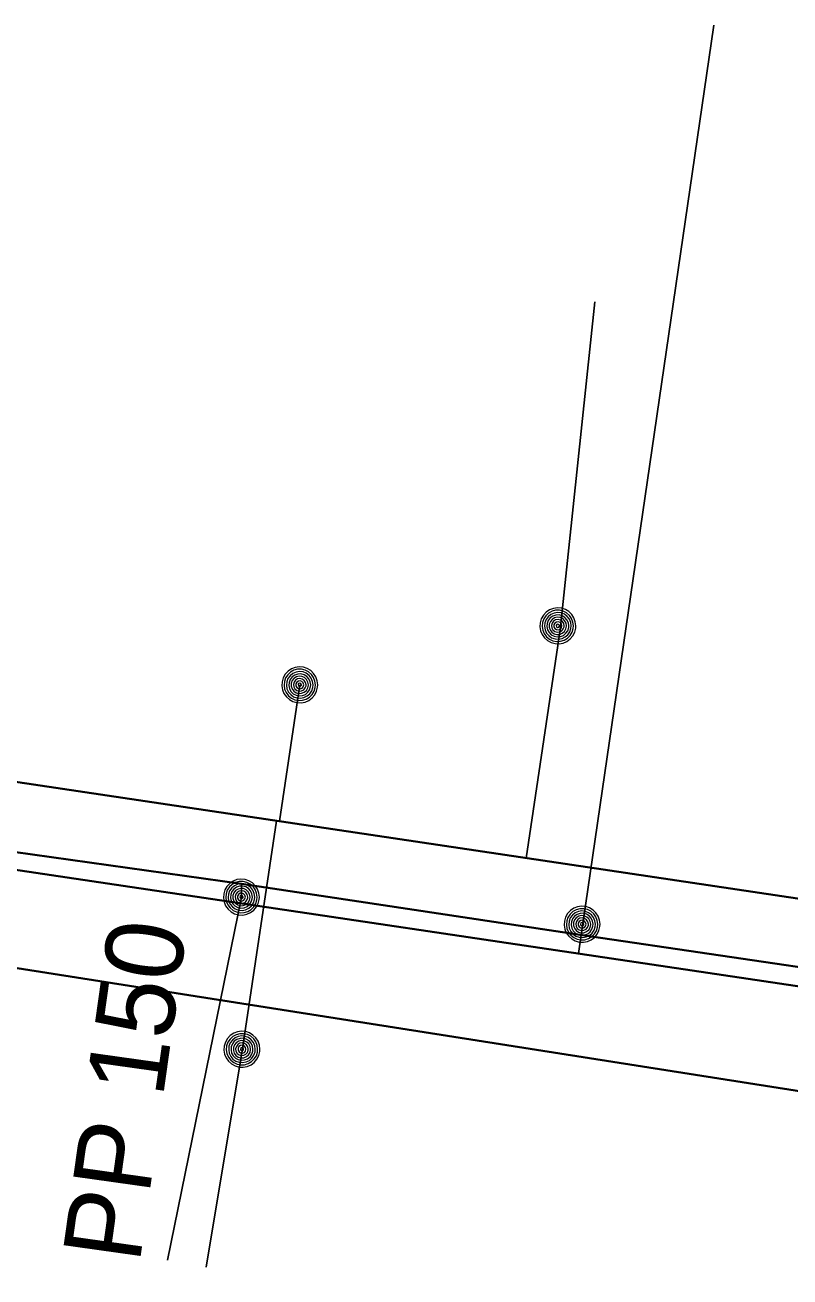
# Model space of a CAD drawing. Extents: x -866761 to -866592, y -1013996 to -1013877.
# Drawn here: x -866692.58 to -866682.75, y -1013971.12 to -1013955.01 of the extents above; entities that cross this region are included whole.
import ezdxf

# ---------------------------------------------------------------- set-up
doc = ezdxf.new("R2010")
doc.units = 0
doc.header["$LTSCALE"] = 0.44
for name, color, linetype, lineweight in [('1', 7, 'Continuous', 35), ('12', 7, 'Continuous', 13), ('21', 7, 'Continuous', 35), ('23', 7, 'Continuous', 25), ('25', 7, 'Continuous', 13), ('3', 7, 'Continuous', 25), ('32', 7, 'Continuous', 13)]:
    doc.layers.add(name, color=color, linetype=linetype, lineweight=lineweight)

msp = doc.modelspace()

# ---------------------------------------------------------------- linework, layer by layer
at = {"layer": '1'}
msp.add_line((-866612.967, -1013977.763), (-866734.931, -1013959.586), dxfattribs=at)
for points in [[(-866612.815, -1013977.108), (-866621.035, -1013976.325), (-866621.378, -1013976.297), (-866626.243, -1013975.519), (-866632.94, -1013974.51), (-866645.03, -1013972.86), (-866647.305, -1013972.501), (-866654.48, -1013971.31), (-866668.882, -1013969.171), (-866678.229, -1013967.78), (-866685.446, -1013966.718), (-866689.8, -1013966.06), (-866697.865, -1013964.927), (-866723.097, -1013961.352), (-866726.923, -1013960.77), (-866727.214, -1013960.734), (-866737.38, -1013959.64), (-866746.09, -1013958.48), (-866747.84, -1013958.25), (-866748.13, -1013958.99), (-866750.15, -1013958.69)], [(-866613.338, -1013979.363), (-866624.951, -1013977.802), (-866715.256, -1013963.593), (-866735.102, -1013960.577)]]:
    msp.add_lwpolyline(points, dxfattribs=at)
at = {"layer": '12'}
for points in [[(-866689.569, -1013966.23), (-866689.575, -1013966.178), (-866689.592, -1013966.128), (-866689.621, -1013966.084), (-866689.658, -1013966.047), (-866689.703, -1013966.02), (-866689.753, -1013966.003), (-866689.806, -1013965.999), (-866689.858, -1013966.006), (-866689.907, -1013966.025), (-866689.95, -1013966.054), (-866689.986, -1013966.093), (-866690.012, -1013966.138), (-866690.028, -1013966.189), (-866690.031, -1013966.241), (-866690.023, -1013966.293), (-866690.003, -1013966.342), (-866689.972, -1013966.385), (-866689.933, -1013966.419), (-866689.887, -1013966.445), (-866689.836, -1013966.459), (-866689.783, -1013966.461), (-866689.732, -1013966.451), (-866689.684, -1013966.43), (-866689.641, -1013966.399), (-866689.607, -1013966.358), (-866689.583, -1013966.312), (-866689.571, -1013966.261)], [(-866689.599, -1013966.23), (-866689.605, -1013966.181), (-866689.622, -1013966.135), (-866689.65, -1013966.095), (-866689.687, -1013966.063), (-866689.731, -1013966.041), (-866689.779, -1013966.03), (-866689.828, -1013966.03), (-866689.875, -1013966.043), (-866689.918, -1013966.067), (-866689.954, -1013966.1), (-866689.981, -1013966.141), (-866689.997, -1013966.188), (-866690.001, -1013966.237), (-866689.994, -1013966.285), (-866689.975, -1013966.33), (-866689.945, -1013966.37), (-866689.907, -1013966.401), (-866689.863, -1013966.421), (-866689.815, -1013966.431), (-866689.766, -1013966.429), (-866689.719, -1013966.414), (-866689.676, -1013966.389), (-866689.642, -1013966.355), (-866689.616, -1013966.313), (-866689.602, -1013966.266)], [(-866689.629, -1013966.23), (-866689.635, -1013966.185), (-866689.652, -1013966.143), (-866689.68, -1013966.108), (-866689.716, -1013966.081), (-866689.758, -1013966.064), (-866689.803, -1013966.059), (-866689.848, -1013966.065), (-866689.889, -1013966.084), (-866689.924, -1013966.112), (-866689.951, -1013966.149), (-866689.967, -1013966.191), (-866689.971, -1013966.236), (-866689.964, -1013966.281), (-866689.945, -1013966.322), (-866689.916, -1013966.356), (-866689.879, -1013966.382), (-866689.836, -1013966.398), (-866689.791, -1013966.401), (-866689.746, -1013966.393), (-866689.706, -1013966.373), (-866689.672, -1013966.344), (-866689.646, -1013966.306), (-866689.632, -1013966.263)], [(-866689.659, -1013966.23), (-866689.664, -1013966.189), (-866689.682, -1013966.152), (-866689.709, -1013966.121), (-866689.744, -1013966.1), (-866689.784, -1013966.089), (-866689.825, -1013966.091), (-866689.864, -1013966.104), (-866689.898, -1013966.128), (-866689.923, -1013966.16), (-866689.938, -1013966.198), (-866689.941, -1013966.239), (-866689.933, -1013966.279), (-866689.913, -1013966.315), (-866689.884, -1013966.344), (-866689.847, -1013966.363), (-866689.807, -1013966.371), (-866689.766, -1013966.367), (-866689.728, -1013966.352), (-866689.696, -1013966.326), (-866689.673, -1013966.292), (-866689.66, -1013966.253)], [(-866689.689, -1013966.23), (-866689.694, -1013966.194), (-866689.712, -1013966.162), (-866689.738, -1013966.137), (-866689.772, -1013966.122), (-866689.808, -1013966.119), (-866689.843, -1013966.127), (-866689.874, -1013966.147), (-866689.897, -1013966.175), (-866689.91, -1013966.209), (-866689.91, -1013966.246), (-866689.899, -1013966.281), (-866689.878, -1013966.31), (-866689.848, -1013966.331), (-866689.813, -1013966.341), (-866689.776, -1013966.339), (-866689.742, -1013966.325), (-866689.715, -1013966.302), (-866689.696, -1013966.27), (-866689.689, -1013966.235)], [(-866689.719, -1013966.23), (-866689.724, -1013966.199), (-866689.741, -1013966.173), (-866689.767, -1013966.156), (-866689.797, -1013966.149), (-866689.828, -1013966.153), (-866689.855, -1013966.17), (-866689.873, -1013966.194), (-866689.881, -1013966.225), (-866689.877, -1013966.255), (-866689.862, -1013966.283), (-866689.838, -1013966.302), (-866689.808, -1013966.311), (-866689.777, -1013966.308), (-866689.749, -1013966.294), (-866689.729, -1013966.27), (-866689.719, -1013966.241)], [(-866689.749, -1013966.23), (-866689.754, -1013966.206), (-866689.771, -1013966.188), (-866689.794, -1013966.179), (-866689.818, -1013966.182), (-866689.839, -1013966.196), (-866689.85, -1013966.218), (-866689.85, -1013966.243), (-866689.838, -1013966.264), (-866689.818, -1013966.278), (-866689.793, -1013966.281), (-866689.77, -1013966.272), (-866689.754, -1013966.254)], [(-866689.779, -1013966.23), (-866689.784, -1013966.215), (-866689.799, -1013966.209), (-866689.814, -1013966.213), (-866689.821, -1013966.227), (-866689.817, -1013966.242), (-866689.804, -1013966.251), (-866689.789, -1013966.248), (-866689.779, -1013966.236)], [(-866685.189, -1013966.58), (-866685.195, -1013966.528), (-866685.212, -1013966.478), (-866685.241, -1013966.434), (-866685.278, -1013966.397), (-866685.323, -1013966.37), (-866685.373, -1013966.353), (-866685.426, -1013966.349), (-866685.478, -1013966.356), (-866685.527, -1013966.375), (-866685.57, -1013966.404), (-866685.606, -1013966.443), (-866685.632, -1013966.488), (-866685.648, -1013966.539), (-866685.651, -1013966.591), (-866685.643, -1013966.643), (-866685.623, -1013966.692), (-866685.592, -1013966.735), (-866685.553, -1013966.769), (-866685.507, -1013966.795), (-866685.456, -1013966.809), (-866685.403, -1013966.811), (-866685.352, -1013966.801), (-866685.304, -1013966.78), (-866685.261, -1013966.749), (-866685.227, -1013966.708), (-866685.203, -1013966.662), (-866685.191, -1013966.611)], [(-866685.219, -1013966.58), (-866685.225, -1013966.531), (-866685.242, -1013966.485), (-866685.27, -1013966.445), (-866685.307, -1013966.413), (-866685.351, -1013966.391), (-866685.399, -1013966.38), (-866685.448, -1013966.38), (-866685.495, -1013966.393), (-866685.538, -1013966.417), (-866685.574, -1013966.45), (-866685.601, -1013966.491), (-866685.617, -1013966.538), (-866685.621, -1013966.587), (-866685.614, -1013966.635), (-866685.595, -1013966.68), (-866685.565, -1013966.72), (-866685.527, -1013966.751), (-866685.483, -1013966.771), (-866685.435, -1013966.781), (-866685.386, -1013966.779), (-866685.339, -1013966.764), (-866685.296, -1013966.739), (-866685.262, -1013966.705), (-866685.236, -1013966.663), (-866685.222, -1013966.616)], [(-866685.249, -1013966.58), (-866685.255, -1013966.535), (-866685.272, -1013966.493), (-866685.3, -1013966.458), (-866685.336, -1013966.431), (-866685.378, -1013966.414), (-866685.423, -1013966.409), (-866685.468, -1013966.415), (-866685.509, -1013966.434), (-866685.544, -1013966.462), (-866685.571, -1013966.499), (-866685.587, -1013966.541), (-866685.591, -1013966.586), (-866685.584, -1013966.631), (-866685.565, -1013966.672), (-866685.536, -1013966.706), (-866685.499, -1013966.732), (-866685.456, -1013966.748), (-866685.411, -1013966.751), (-866685.366, -1013966.743), (-866685.326, -1013966.723), (-866685.292, -1013966.694), (-866685.266, -1013966.656), (-866685.252, -1013966.613)], [(-866685.279, -1013966.58), (-866685.284, -1013966.539), (-866685.302, -1013966.502), (-866685.329, -1013966.471), (-866685.364, -1013966.45), (-866685.404, -1013966.439), (-866685.445, -1013966.441), (-866685.484, -1013966.454), (-866685.518, -1013966.478), (-866685.543, -1013966.51), (-866685.558, -1013966.548), (-866685.561, -1013966.589), (-866685.553, -1013966.629), (-866685.533, -1013966.665), (-866685.504, -1013966.694), (-866685.467, -1013966.713), (-866685.427, -1013966.721), (-866685.386, -1013966.717), (-866685.348, -1013966.702), (-866685.316, -1013966.676), (-866685.293, -1013966.642), (-866685.28, -1013966.603)], [(-866685.309, -1013966.58), (-866685.314, -1013966.544), (-866685.332, -1013966.512), (-866685.358, -1013966.487), (-866685.392, -1013966.472), (-866685.428, -1013966.469), (-866685.463, -1013966.477), (-866685.494, -1013966.497), (-866685.517, -1013966.525), (-866685.53, -1013966.559), (-866685.53, -1013966.596), (-866685.519, -1013966.631), (-866685.498, -1013966.66), (-866685.468, -1013966.681), (-866685.433, -1013966.691), (-866685.396, -1013966.689), (-866685.362, -1013966.675), (-866685.335, -1013966.652), (-866685.316, -1013966.62), (-866685.309, -1013966.585)], [(-866685.339, -1013966.58), (-866685.344, -1013966.549), (-866685.361, -1013966.523), (-866685.387, -1013966.506), (-866685.417, -1013966.499), (-866685.448, -1013966.503), (-866685.475, -1013966.52), (-866685.493, -1013966.544), (-866685.501, -1013966.575), (-866685.497, -1013966.605), (-866685.482, -1013966.633), (-866685.458, -1013966.652), (-866685.428, -1013966.661), (-866685.397, -1013966.658), (-866685.369, -1013966.644), (-866685.349, -1013966.62), (-866685.339, -1013966.591)], [(-866685.369, -1013966.58), (-866685.374, -1013966.556), (-866685.391, -1013966.538), (-866685.414, -1013966.529), (-866685.438, -1013966.532), (-866685.459, -1013966.546), (-866685.47, -1013966.568), (-866685.47, -1013966.593), (-866685.458, -1013966.614), (-866685.438, -1013966.628), (-866685.413, -1013966.631), (-866685.39, -1013966.622), (-866685.374, -1013966.604)], [(-866685.399, -1013966.58), (-866685.404, -1013966.565), (-866685.419, -1013966.559), (-866685.434, -1013966.563), (-866685.441, -1013966.577), (-866685.437, -1013966.592), (-866685.424, -1013966.601), (-866685.409, -1013966.598), (-866685.399, -1013966.586)]]:
    msp.add_lwpolyline(points, close=True, dxfattribs=at)
at = {"layer": '21'}
msp.add_line((-866709.04, -1013962.31), (-866647.459, -1013971.5), dxfattribs=at)
at = {"layer": '23'}
msp.add_line((-866689.312, -1013965.254), (-866689.05, -1013963.5), dxfattribs=at)
for points in [[(-866686.138, -1013965.728), (-866685.7, -1013962.79), (-866685.254, -1013958.573)], [(-866689.348, -1013965.249), (-866689.79, -1013968.21), (-866690.252, -1013970.99)]]:
    msp.add_lwpolyline(points, dxfattribs=at)
at = {"layer": '25'}
for points in [[(-866688.819, -1013963.5), (-866688.825, -1013963.448), (-866688.842, -1013963.398), (-866688.871, -1013963.354), (-866688.908, -1013963.317), (-866688.953, -1013963.29), (-866689.003, -1013963.273), (-866689.056, -1013963.269), (-866689.108, -1013963.276), (-866689.157, -1013963.295), (-866689.2, -1013963.324), (-866689.236, -1013963.363), (-866689.262, -1013963.408), (-866689.278, -1013963.459), (-866689.281, -1013963.511), (-866689.273, -1013963.563), (-866689.253, -1013963.612), (-866689.222, -1013963.655), (-866689.183, -1013963.689), (-866689.137, -1013963.715), (-866689.086, -1013963.729), (-866689.033, -1013963.731), (-866688.982, -1013963.721), (-866688.934, -1013963.7), (-866688.891, -1013963.669), (-866688.857, -1013963.628), (-866688.833, -1013963.582), (-866688.821, -1013963.531)], [(-866688.849, -1013963.5), (-866688.855, -1013963.451), (-866688.872, -1013963.405), (-866688.9, -1013963.365), (-866688.937, -1013963.333), (-866688.981, -1013963.311), (-866689.029, -1013963.3), (-866689.078, -1013963.3), (-866689.125, -1013963.313), (-866689.168, -1013963.337), (-866689.204, -1013963.37), (-866689.231, -1013963.411), (-866689.247, -1013963.458), (-866689.251, -1013963.507), (-866689.244, -1013963.555), (-866689.225, -1013963.6), (-866689.195, -1013963.64), (-866689.157, -1013963.671), (-866689.113, -1013963.691), (-866689.065, -1013963.701), (-866689.016, -1013963.699), (-866688.969, -1013963.684), (-866688.926, -1013963.659), (-866688.892, -1013963.625), (-866688.866, -1013963.583), (-866688.852, -1013963.536)], [(-866688.879, -1013963.5), (-866688.885, -1013963.455), (-866688.902, -1013963.413), (-866688.93, -1013963.378), (-866688.966, -1013963.351), (-866689.008, -1013963.334), (-866689.053, -1013963.329), (-866689.098, -1013963.335), (-866689.139, -1013963.354), (-866689.174, -1013963.382), (-866689.201, -1013963.419), (-866689.217, -1013963.461), (-866689.221, -1013963.506), (-866689.214, -1013963.551), (-866689.195, -1013963.592), (-866689.166, -1013963.626), (-866689.129, -1013963.652), (-866689.086, -1013963.668), (-866689.041, -1013963.671), (-866688.996, -1013963.663), (-866688.956, -1013963.643), (-866688.922, -1013963.614), (-866688.896, -1013963.576), (-866688.882, -1013963.533)], [(-866688.909, -1013963.5), (-866688.914, -1013963.459), (-866688.932, -1013963.422), (-866688.959, -1013963.391), (-866688.994, -1013963.37), (-866689.034, -1013963.359), (-866689.075, -1013963.361), (-866689.114, -1013963.374), (-866689.148, -1013963.398), (-866689.173, -1013963.43), (-866689.188, -1013963.468), (-866689.191, -1013963.509), (-866689.183, -1013963.549), (-866689.163, -1013963.585), (-866689.134, -1013963.614), (-866689.097, -1013963.633), (-866689.057, -1013963.641), (-866689.016, -1013963.637), (-866688.978, -1013963.622), (-866688.946, -1013963.596), (-866688.923, -1013963.562), (-866688.91, -1013963.523)], [(-866688.939, -1013963.5), (-866688.944, -1013963.464), (-866688.962, -1013963.432), (-866688.988, -1013963.407), (-866689.022, -1013963.392), (-866689.058, -1013963.389), (-866689.093, -1013963.397), (-866689.124, -1013963.417), (-866689.147, -1013963.445), (-866689.16, -1013963.479), (-866689.16, -1013963.516), (-866689.149, -1013963.551), (-866689.128, -1013963.58), (-866689.098, -1013963.601), (-866689.063, -1013963.611), (-866689.026, -1013963.609), (-866688.992, -1013963.595), (-866688.965, -1013963.572), (-866688.946, -1013963.54), (-866688.939, -1013963.505)], [(-866688.969, -1013963.5), (-866688.974, -1013963.469), (-866688.991, -1013963.443), (-866689.017, -1013963.426), (-866689.047, -1013963.419), (-866689.078, -1013963.423), (-866689.105, -1013963.44), (-866689.123, -1013963.464), (-866689.131, -1013963.495), (-866689.127, -1013963.525), (-866689.112, -1013963.553), (-866689.088, -1013963.572), (-866689.058, -1013963.581), (-866689.027, -1013963.578), (-866688.999, -1013963.564), (-866688.979, -1013963.54), (-866688.969, -1013963.511)], [(-866688.999, -1013963.5), (-866689.004, -1013963.476), (-866689.021, -1013963.458), (-866689.044, -1013963.449), (-866689.068, -1013963.452), (-866689.089, -1013963.466), (-866689.1, -1013963.488), (-866689.1, -1013963.513), (-866689.088, -1013963.534), (-866689.068, -1013963.548), (-866689.043, -1013963.551), (-866689.02, -1013963.542), (-866689.004, -1013963.524)], [(-866689.029, -1013963.5), (-866689.034, -1013963.485), (-866689.049, -1013963.479), (-866689.064, -1013963.483), (-866689.071, -1013963.497), (-866689.067, -1013963.512), (-866689.054, -1013963.521), (-866689.039, -1013963.518), (-866689.029, -1013963.506)]]:
    msp.add_lwpolyline(points, close=True, dxfattribs=at)
at = {"layer": '3'}
msp.add_line((-866685.465, -1013966.958), (-866683.726, -1013955.011), dxfattribs=at)
msp.add_lwpolyline([(-866689.8, -1013966.06), (-866689.8, -1013966.23), (-866690.75, -1013970.9)], dxfattribs=at)
at = {"layer": '32'}
for points in [[(-866685.5, -1013962.741), (-866685.507, -1013962.689), (-866685.524, -1013962.639), (-866685.553, -1013962.595), (-866685.59, -1013962.558), (-866685.635, -1013962.531), (-866685.684, -1013962.514), (-866685.738, -1013962.51), (-866685.789, -1013962.517), (-866685.838, -1013962.536), (-866685.882, -1013962.565), (-866685.918, -1013962.604), (-866685.944, -1013962.649), (-866685.96, -1013962.7), (-866685.963, -1013962.752), (-866685.955, -1013962.804), (-866685.934, -1013962.853), (-866685.904, -1013962.896), (-866685.865, -1013962.93), (-866685.819, -1013962.956), (-866685.767, -1013962.97), (-866685.715, -1013962.972), (-866685.664, -1013962.962), (-866685.615, -1013962.941), (-866685.573, -1013962.91), (-866685.539, -1013962.869), (-866685.515, -1013962.823), (-866685.502, -1013962.772)], [(-866685.531, -1013962.741), (-866685.537, -1013962.692), (-866685.554, -1013962.646), (-866685.581, -1013962.606), (-866685.619, -1013962.574), (-866685.663, -1013962.552), (-866685.711, -1013962.541), (-866685.76, -1013962.541), (-866685.806, -1013962.554), (-866685.85, -1013962.578), (-866685.886, -1013962.611), (-866685.913, -1013962.652), (-866685.929, -1013962.699), (-866685.933, -1013962.748), (-866685.926, -1013962.796), (-866685.907, -1013962.841), (-866685.877, -1013962.881), (-866685.838, -1013962.912), (-866685.794, -1013962.932), (-866685.747, -1013962.942), (-866685.698, -1013962.94), (-866685.651, -1013962.925), (-866685.608, -1013962.9), (-866685.573, -1013962.866), (-866685.548, -1013962.824), (-866685.534, -1013962.777)], [(-866685.561, -1013962.741), (-866685.566, -1013962.696), (-866685.583, -1013962.654), (-866685.612, -1013962.619), (-866685.647, -1013962.592), (-866685.69, -1013962.575), (-866685.735, -1013962.57), (-866685.779, -1013962.576), (-866685.821, -1013962.595), (-866685.855, -1013962.623), (-866685.882, -1013962.66), (-866685.899, -1013962.702), (-866685.902, -1013962.747), (-866685.896, -1013962.792), (-866685.877, -1013962.833), (-866685.848, -1013962.867), (-866685.811, -1013962.893), (-866685.767, -1013962.909), (-866685.723, -1013962.912), (-866685.678, -1013962.904), (-866685.637, -1013962.884), (-866685.603, -1013962.855), (-866685.578, -1013962.817), (-866685.564, -1013962.774)], [(-866685.591, -1013962.741), (-866685.595, -1013962.7), (-866685.614, -1013962.663), (-866685.641, -1013962.632), (-866685.676, -1013962.611), (-866685.716, -1013962.6), (-866685.757, -1013962.602), (-866685.796, -1013962.615), (-866685.83, -1013962.639), (-866685.855, -1013962.671), (-866685.87, -1013962.709), (-866685.872, -1013962.75), (-866685.865, -1013962.79), (-866685.845, -1013962.826), (-866685.816, -1013962.855), (-866685.779, -1013962.874), (-866685.739, -1013962.882), (-866685.698, -1013962.878), (-866685.659, -1013962.863), (-866685.627, -1013962.837), (-866685.605, -1013962.803), (-866685.592, -1013962.764)], [(-866685.62, -1013962.741), (-866685.625, -1013962.705), (-866685.644, -1013962.673), (-866685.669, -1013962.648), (-866685.703, -1013962.633), (-866685.74, -1013962.63), (-866685.774, -1013962.638), (-866685.806, -1013962.658), (-866685.828, -1013962.686), (-866685.842, -1013962.72), (-866685.842, -1013962.757), (-866685.831, -1013962.792), (-866685.809, -1013962.821), (-866685.779, -1013962.842), (-866685.745, -1013962.852), (-866685.708, -1013962.85), (-866685.674, -1013962.836), (-866685.647, -1013962.813), (-866685.627, -1013962.781), (-866685.62, -1013962.746)], [(-866685.651, -1013962.741), (-866685.656, -1013962.71), (-866685.673, -1013962.684), (-866685.698, -1013962.667), (-866685.728, -1013962.66), (-866685.76, -1013962.664), (-866685.787, -1013962.681), (-866685.804, -1013962.705), (-866685.813, -1013962.736), (-866685.809, -1013962.766), (-866685.794, -1013962.794), (-866685.769, -1013962.813), (-866685.74, -1013962.822), (-866685.708, -1013962.819), (-866685.681, -1013962.805), (-866685.661, -1013962.781), (-866685.651, -1013962.752)], [(-866685.681, -1013962.741), (-866685.686, -1013962.717), (-866685.703, -1013962.699), (-866685.725, -1013962.69), (-866685.75, -1013962.693), (-866685.771, -1013962.707), (-866685.782, -1013962.729), (-866685.782, -1013962.754), (-866685.769, -1013962.775), (-866685.75, -1013962.789), (-866685.725, -1013962.792), (-866685.701, -1013962.783), (-866685.686, -1013962.765)], [(-866685.711, -1013962.741), (-866685.716, -1013962.726), (-866685.73, -1013962.72), (-866685.745, -1013962.724), (-866685.752, -1013962.738), (-866685.749, -1013962.753), (-866685.735, -1013962.762), (-866685.72, -1013962.759), (-866685.711, -1013962.747)], [(-866689.561, -1013968.188), (-866689.568, -1013968.136), (-866689.585, -1013968.086), (-866689.614, -1013968.042), (-866689.651, -1013968.005), (-866689.696, -1013967.978), (-866689.745, -1013967.961), (-866689.799, -1013967.957), (-866689.85, -1013967.964), (-866689.899, -1013967.983), (-866689.943, -1013968.012), (-866689.978, -1013968.051), (-866690.005, -1013968.096), (-866690.021, -1013968.147), (-866690.024, -1013968.199), (-866690.016, -1013968.251), (-866689.995, -1013968.3), (-866689.965, -1013968.343), (-866689.926, -1013968.377), (-866689.88, -1013968.403), (-866689.828, -1013968.417), (-866689.776, -1013968.419), (-866689.725, -1013968.409), (-866689.676, -1013968.388), (-866689.634, -1013968.357), (-866689.6, -1013968.316), (-866689.576, -1013968.27), (-866689.563, -1013968.219)], [(-866689.592, -1013968.188), (-866689.598, -1013968.139), (-866689.615, -1013968.093), (-866689.642, -1013968.053), (-866689.679, -1013968.021), (-866689.723, -1013967.999), (-866689.772, -1013967.988), (-866689.821, -1013967.988), (-866689.867, -1013968.001), (-866689.911, -1013968.025), (-866689.946, -1013968.058), (-866689.973, -1013968.099), (-866689.99, -1013968.146), (-866689.994, -1013968.195), (-866689.987, -1013968.243), (-866689.968, -1013968.288), (-866689.938, -1013968.328), (-866689.899, -1013968.359), (-866689.855, -1013968.379), (-866689.808, -1013968.389), (-866689.759, -1013968.387), (-866689.712, -1013968.372), (-866689.669, -1013968.347), (-866689.634, -1013968.313), (-866689.608, -1013968.271), (-866689.595, -1013968.224)], [(-866689.622, -1013968.188), (-866689.627, -1013968.143), (-866689.644, -1013968.101), (-866689.673, -1013968.066), (-866689.708, -1013968.039), (-866689.75, -1013968.022), (-866689.796, -1013968.017), (-866689.84, -1013968.023), (-866689.882, -1013968.042), (-866689.916, -1013968.07), (-866689.943, -1013968.107), (-866689.96, -1013968.149), (-866689.963, -1013968.194), (-866689.956, -1013968.239), (-866689.938, -1013968.28), (-866689.909, -1013968.314), (-866689.872, -1013968.34), (-866689.828, -1013968.356), (-866689.784, -1013968.359), (-866689.739, -1013968.351), (-866689.698, -1013968.331), (-866689.664, -1013968.302), (-866689.639, -1013968.264), (-866689.625, -1013968.221)], [(-866689.652, -1013968.188), (-866689.656, -1013968.147), (-866689.674, -1013968.11), (-866689.701, -1013968.079), (-866689.737, -1013968.058), (-866689.777, -1013968.047), (-866689.818, -1013968.049), (-866689.857, -1013968.062), (-866689.891, -1013968.086), (-866689.916, -1013968.118), (-866689.931, -1013968.156), (-866689.933, -1013968.197), (-866689.926, -1013968.237), (-866689.906, -1013968.273), (-866689.877, -1013968.302), (-866689.84, -1013968.321), (-866689.799, -1013968.329), (-866689.759, -1013968.325), (-866689.72, -1013968.31), (-866689.688, -1013968.284), (-866689.666, -1013968.25), (-866689.652, -1013968.211)], [(-866689.681, -1013968.188), (-866689.686, -1013968.152), (-866689.705, -1013968.12), (-866689.73, -1013968.095), (-866689.764, -1013968.08), (-866689.801, -1013968.077), (-866689.835, -1013968.085), (-866689.867, -1013968.105), (-866689.889, -1013968.133), (-866689.902, -1013968.167), (-866689.902, -1013968.204), (-866689.892, -1013968.239), (-866689.87, -1013968.268), (-866689.84, -1013968.289), (-866689.806, -1013968.299), (-866689.769, -1013968.297), (-866689.735, -1013968.283), (-866689.708, -1013968.26), (-866689.688, -1013968.228), (-866689.681, -1013968.193)], [(-866689.712, -1013968.188), (-866689.717, -1013968.157), (-866689.733, -1013968.131), (-866689.759, -1013968.114), (-866689.789, -1013968.107), (-866689.821, -1013968.111), (-866689.848, -1013968.128), (-866689.865, -1013968.152), (-866689.874, -1013968.183), (-866689.87, -1013968.213), (-866689.855, -1013968.241), (-866689.83, -1013968.26), (-866689.801, -1013968.269), (-866689.769, -1013968.266), (-866689.742, -1013968.252), (-866689.722, -1013968.228), (-866689.712, -1013968.199)], [(-866689.742, -1013968.188), (-866689.747, -1013968.164), (-866689.764, -1013968.146), (-866689.786, -1013968.137), (-866689.811, -1013968.14), (-866689.831, -1013968.154), (-866689.843, -1013968.176), (-866689.843, -1013968.201), (-866689.83, -1013968.222), (-866689.811, -1013968.236), (-866689.786, -1013968.239), (-866689.762, -1013968.23), (-866689.747, -1013968.212)], [(-866689.772, -1013968.188), (-866689.777, -1013968.173), (-866689.791, -1013968.167), (-866689.806, -1013968.171), (-866689.813, -1013968.185), (-866689.809, -1013968.2), (-866689.796, -1013968.209), (-866689.781, -1013968.206), (-866689.772, -1013968.194)]]:
    msp.add_lwpolyline(points, close=True, dxfattribs=at)

# ---------------------------------------------------------------- texts
at = {"layer": '23'}
msp.add_text('PP 150', height=1, rotation=82, dxfattribs=at).set_placement((-866691.11, -1013970.957))

doc.saveas('drawing.dxf')
